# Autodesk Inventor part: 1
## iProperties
Shininess: 20.0
Length Units: 11270
Angle Units: 11279
Time Units: 11290
Mass Units: 11283
Length Display Precision: 3
Angle Display Precision: 2
Created: 2000-10
Part Number: 1
Material: Par défaut
Document SubType Name: Modélisation
Density: 0.0
Volumn: 0.0
Area: 0.0
PropertySet Name: Model Information
Control State: 0
Master: False
Checked Out: False
Author: Laurent GAUTHERON
